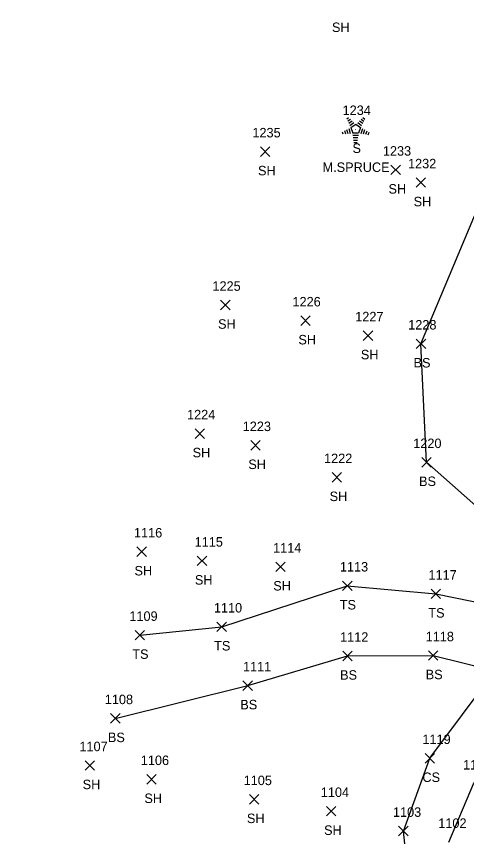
# Model space of a CAD drawing. Extents: x 1554917 to 1555870, y 813367 to 816333.
# Drawn here: x 1554928.5 to 1555023.3, y 813586.9 to 813759.7 of the extents above; entities that cross this region are included whole.
import ezdxf

# ---------------------------------------------------------------- set-up
doc = ezdxf.new("R2010")
doc.units = 0
for name, color, linetype in [('L_A', 7, 'Continuous'), ('L_C', 7, 'Continuous'), ('L_I', 7, 'Continuous'), ('L_TIC', 7, 'Continuous'), ('LELB', 7, 'Continuous'), ('LTC', 7, 'Continuous')]:
    doc.layers.add(name, color=color, linetype=linetype)

msp = doc.modelspace()

# ---------------------------------------------------------------- linework, layer by layer
at = {"layer": 'L_TIC'}
for points in [[(1554979.89, 813730.18), (1554981.89, 813732.18)], [(1554981.89, 813730.18), (1554979.89, 813732.18)], [(1555007.37, 813726.33), (1555009.37, 813728.33)], [(1555009.37, 813726.33), (1555007.37, 813728.33)], [(1555012.65, 813723.66), (1555014.65, 813725.66)], [(1555014.65, 813723.66), (1555012.65, 813725.66)], [(1554971.49, 813697.86), (1554973.49, 813699.86)], [(1554973.49, 813697.86), (1554971.49, 813699.86)], [(1554988.39, 813694.56), (1554990.39, 813696.56)], [(1554990.39, 813694.56), (1554988.39, 813696.56)], [(1555001.54, 813691.42), (1555003.54, 813693.42)], [(1555003.54, 813691.42), (1555001.54, 813693.42)], [(1555012.69, 813689.7), (1555014.69, 813691.7)], [(1555014.69, 813689.7), (1555012.69, 813691.7)], [(1554966.13, 813670.77), (1554968.13, 813672.77)], [(1554968.13, 813670.77), (1554966.13, 813672.77)], [(1554977.85, 813668.3), (1554979.85, 813670.3)], [(1554979.85, 813668.3), (1554977.85, 813670.3)], [(1555013.84, 813664.72), (1555015.84, 813666.72)], [(1555015.84, 813664.72), (1555013.84, 813666.72)], [(1554994.97, 813661.55), (1554996.97, 813663.55)], [(1554996.97, 813661.55), (1554994.97, 813663.55)], [(1554953.89, 813645.88), (1554955.89, 813647.88)], [(1554955.89, 813645.88), (1554953.89, 813647.88)], [(1554966.6, 813643.95), (1554968.6, 813645.95)], [(1554968.6, 813643.95), (1554966.6, 813645.95)], [(1554983.11, 813642.71), (1554985.11, 813644.71)], [(1554985.11, 813642.71), (1554983.11, 813644.71)], [(1554997.18, 813638.71), (1554999.18, 813640.71)], [(1554999.18, 813638.71), (1554997.18, 813640.71)], [(1555015.83, 813637), (1555017.83, 813639)], [(1555017.83, 813637), (1555015.83, 813639)], [(1554970.74, 813630.07), (1554972.74, 813632.07)], [(1554972.74, 813630.07), (1554970.74, 813632.07)], [(1554953.51, 813628.31), (1554955.51, 813630.31)], [(1554955.51, 813628.31), (1554953.51, 813630.31)], [(1554997.22, 813623.91), (1554999.22, 813625.91)], [(1554999.22, 813623.91), (1554997.22, 813625.91)], [(1555015.24, 813624.01), (1555017.24, 813626.01)], [(1555017.24, 813624.01), (1555015.24, 813626.01)], [(1554976.21, 813617.67), (1554978.21, 813619.67)], [(1554978.21, 813617.67), (1554976.21, 813619.67)], [(1554948.33, 813610.76), (1554950.33, 813612.76)], [(1554950.33, 813610.76), (1554948.33, 813612.76)], [(1554942.99, 813600.85), (1554944.99, 813602.85)], [(1554944.99, 813600.85), (1554942.99, 813602.85)], [(1555014.55, 813602.36), (1555016.55, 813604.36)], [(1555016.55, 813602.36), (1555014.55, 813604.36)], [(1554955.97, 813597.93), (1554957.97, 813599.93)], [(1554957.97, 813597.93), (1554955.97, 813599.93)], [(1554977.56, 813593.7), (1554979.56, 813595.7)], [(1554979.56, 813593.7), (1554977.56, 813595.7)], [(1554993.8, 813591.21), (1554995.8, 813593.21)], [(1554995.8, 813591.21), (1554993.8, 813593.21)], [(1555008.99, 813587.02), (1555010.99, 813589.02)], [(1555010.99, 813587.02), (1555008.99, 813589.02)]]:
    msp.add_lwpolyline(points, dxfattribs=at)
at = {"layer": 'LELB'}
for points in [[(1555019.54, 813585.69), (1555024.77, 813597.99), (1555042.65, 813620.9), (1555048.58, 813631.85), (1555066.52, 813674.6), (1555093.66, 813750.68), (1555103.98, 813778.92), (1555100.94, 813788.26), (1555095.86, 813797.4), (1555100.34, 813804.26), (1555113.07, 813834.65), (1555120.88, 813859.4), (1555126.12, 813877.4), (1555144.96, 813909.35), (1555149.61, 813919.5), (1555153.95, 813930.09), (1555158.29, 813940)], [(1554949.33, 813611.76), (1554977.21, 813618.67), (1554998.22, 813624.91), (1555016.24, 813625.01), (1555029.3, 813621.81), (1555040.32, 813624.75), (1555045.98, 813633.07), (1555049.32, 813640.6), (1555063.34, 813676.25), (1555081.89, 813724.28), (1555091.18, 813752.08), (1555095.69, 813774.96), (1555088.32, 813786.78), (1555082.82, 813809.08), (1555086.32, 813807.6), (1555081.46, 813811.86)], [(1554954.51, 813629.31), (1554971.74, 813631.07), (1554998.18, 813639.71), (1555016.83, 813638), (1555031.95, 813634.95), (1555041.94, 813634.59), (1555045.91, 813643.15), (1555048.09, 813658.42), (1555054.81, 813682.71), (1555073.55, 813727.86), (1555077.68, 813738.56), (1555087.17, 813753.94), (1555095.69, 813774.96)], [(1555045.91, 813643.15), (1555028.26, 813653.89), (1555014.84, 813665.72), (1555013.69, 813690.7), (1555025.72, 813719.45), (1555039.73, 813739.79), (1555060.31, 813748.49), (1555087.17, 813753.94)], [(1554928.52, 813569.72), (1554947.56, 813564.37), (1554964.46, 813556.66), (1554984.28, 813565), (1554997.17, 813568.08), (1555012.26, 813566.6), (1555009.99, 813588.02), (1555015.55, 813603.36), (1555029.3, 813621.81)]]:
    msp.add_lwpolyline(points, dxfattribs=at)
at = {"layer": 'LTC'}
for p, q in [((1554998.08, 813738.11), (1554998.44, 813738.36)), ((1554998.29, 813737.64), (1554998.82, 813738.02)), ((1554998.5, 813737.17), (1554999.2, 813737.69)), ((1555000.74, 813737.65), (1555001.42, 813737.16)), ((1555001.11, 813738), (1555001.66, 813737.6)), ((1555001.48, 813738.35), (1555001.9, 813738.04)), ((1554998.02, 813735.82), (1554998.3, 813734.98)), ((1554998.48, 813736.03), (1554998.81, 813735.01)), ((1554998.71, 813736.71), (1554999.59, 813737.35)), ((1554998.93, 813736.25), (1554999.95, 813736.99)), ((1554998.93, 813736.25), (1554999.32, 813735.06)), ((1554999.95, 813736.99), (1555000.94, 813736.26)), ((1555000.37, 813737.3), (1555001.18, 813736.71)), ((1555000.94, 813736.26), (1555000.55, 813735.06)), ((1555001.38, 813735.99), (1555001.04, 813734.95)), ((1555001.83, 813735.74), (1555001.54, 813734.86)), ((1554997.11, 813735.38), (1554997.27, 813734.92)), ((1554997.57, 813735.6), (1554997.78, 813734.95)), ((1555000.55, 813735.06), (1554999.32, 813735.06)), ((1555000.51, 813734.56), (1554999.37, 813734.56)), ((1555000.43, 813734.06), (1554999.44, 813734.06)), ((1555002.27, 813735.49), (1555002.03, 813734.76)), ((1555002.71, 813735.24), (1555002.53, 813734.67)), ((1555000.35, 813733.56), (1554999.51, 813733.56)), ((1555000.26, 813733.06), (1554999.59, 813733.06))]:
    msp.add_line(p, q, dxfattribs=at)

# ---------------------------------------------------------------- texts
at = {"layer": 'L_A'}
for s, p in [('SH', (1554994.95, 813756.38)), ('S', (1554999.27, 813730.9)), ('SH', (1554979.38, 813726.18)), ('SH', (1555006.85, 813722.33)), ('SH', (1555012.14, 813719.66)), ('SH', (1554970.97, 813693.86)), ('SH', (1554987.88, 813690.56)), ('SH', (1555001.03, 813687.42)), ('BS', (1555012.13, 813685.7)), ('SH', (1554965.62, 813666.77)), ('SH', (1554977.34, 813664.3)), ('BS', (1555013.28, 813660.72)), ('SH', (1554994.46, 813657.55)), ('SH', (1554953.38, 813641.88)), ('SH', (1554966.09, 813639.95)), ('SH', (1554982.6, 813638.71)), ('TS', (1554996.59, 813634.71)), ('TS', (1555015.24, 813633)), ('TS', (1554970.15, 813626.07)), ('TS', (1554952.92, 813624.31)), ('BS', (1554996.66, 813619.91)), ('BS', (1555014.68, 813620.01)), ('BS', (1554975.65, 813613.67)), ('BS', (1554947.78, 813606.76)), ('CS', (1555013.99, 813598.36)), ('SH', (1554942.47, 813596.85)), ('SH', (1554955.46, 813593.93)), ('SH', (1554977.05, 813589.7)), ('SH', (1554993.29, 813587.21))]:
    msp.add_text(s, height=2, dxfattribs=at).set_placement(p)
at = {"layer": 'L_C'}
msp.add_text('M.SPRUCE', height=2, dxfattribs=at).set_placement((1554992.97, 813726.9))
at = {"layer": 'L_I'}
for s, p in [('1234', (1554997.19, 813738.9)), ('1235', (1554978.2, 813734.18)), ('1233', (1555005.67, 813730.33)), ('1232', (1555010.96, 813727.66)), ('1225', (1554969.79, 813701.86)), ('1226', (1554986.64, 813698.56)), ('1227', (1554999.85, 813695.42)), ('1228', (1555011, 813693.7)), ('1224', (1554964.44, 813674.77)), ('1223', (1554976.16, 813672.3)), ('1220', (1555012.06, 813668.72)), ('1222', (1554993.28, 813665.55)), ('1116', (1554953.27, 813649.88)), ('1115', (1554966.04, 813647.95)), ('1114', (1554982.56, 813646.71)), ('1113', (1554996.62, 813642.71)), ('1117', (1555015.27, 813641)), ('1110', (1554970.09, 813634.07)), ('1109', (1554952.3, 813632.31)), ('1112', (1554996.66, 813627.91)), ('1118', (1555014.68, 813628.01)), ('1111', (1554976.22, 813621.67)), ('1108', (1554947.13, 813614.76)), ('1119', (1555013.99, 813606.36)), ('1107', (1554941.78, 813604.85)), ('1106', (1554954.71, 813601.93)), ('1120', (1555022.56, 813600.99)), ('1105', (1554976.36, 813597.7)), ('1104', (1554992.6, 813595.21)), ('1103', (1555007.79, 813591.02)), ('1102', (1555017.33, 813588.69))]:
    msp.add_text(s, height=2, dxfattribs=at).set_placement(p)
at = {"layer": 'LTC'}
msp.add_text('.', height=1.04, rotation=270, dxfattribs=at).set_placement((1554999.83, 813736))

doc.saveas('drawing.dxf')
